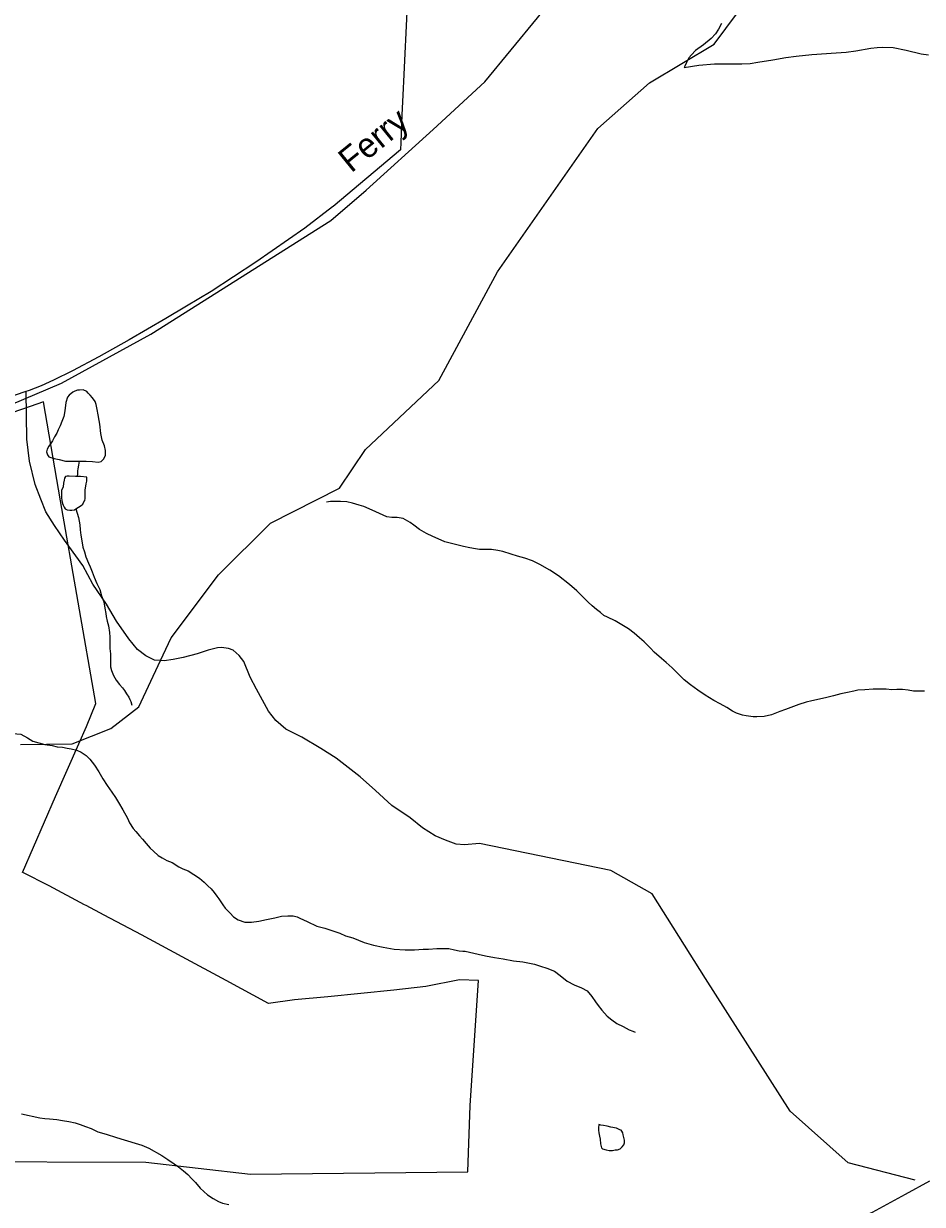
# Model space of a CAD drawing. Extents: x 2001466 to 2224147, y 644118 to 847247.
# Drawn here: x 2037237 to 2040702, y 678885 to 683440 of the extents above; entities that cross this region are included whole.
import ezdxf

# ---------------------------------------------------------------- set-up
doc = ezdxf.new("R2010")
doc.units = 0
for name, color, linetype in [('Exist Boundary Political City Limit New', 7, 'Continuous'), ('Exist Hydrographic Creek Single Shore', 7, 'Continuous'), ('Exist Hydrographic Misc Water Feature', 7, 'Continuous'), ('Exist Road Non-System Type 51', 7, 'Continuous'), ('Exist Road Secondary Type 51 Attributed', 7, 'Continuous'), ('Exist Road Secondary Type 51 Label', 7, 'Continuous'), ('Map Preparation Boundary City Limit Buffer Line', 7, 'Continuous')]:
    doc.layers.add(name, color=color, linetype=linetype)

msp = doc.modelspace()

# ---------------------------------------------------------------- linework, layer by layer
at = {"layer": 'Exist Boundary Political City Limit New'}
for points in [[(2038714.6, 683485), (2038710.9, 683404.7), (2038707.1, 683324.4), (2038703.2, 683244), (2038699.6, 683163.7), (2038696, 683087.9), (2038691, 682980.7), (2038689.8, 682952.9), (2038430.9, 682734.6), (2038428.2, 682732.4), (2038321.1, 682650.8), (2038132.5, 682519), (2037960.8, 682406.2), (2037865.8, 682349.6), (2037786.2, 682302.3), (2037644.4, 682220.5), (2037526.8, 682154.3), (2037426.1, 682100.1), (2037353.2, 682064.7), (2037305.1, 682042.2), (2037258.2, 682024.7), (2037242.6, 682018.8), (2037174.8, 681995.6)], [(2037233.6, 680165.6), (2037360.4, 680457.7), (2037450.4, 680661.2), (2037479.5, 680728.1), (2037515.2, 680816.6), (2037379.6, 681598.4), (2037314, 681981.4), (2037262.9, 681962.2), (2037192.5, 681938.2)], [(2036944.8, 679049.9), (2037709, 679048.1), (2038111.9, 679001), (2038950.1, 679011), (2038959.2, 679266.2), (2038990.4, 679748.1), (2038917.5, 679751), (2038787.4, 679725.1), (2038664.1, 679711.7), (2038410.5, 679685.1), (2038281.6, 679673.3), (2038181.6, 679660.1), (2038018.1, 679748.5), (2037848.8, 679840.4), (2037691.6, 679925.2), (2037547.5, 680000), (2037478, 680037.8), (2037472.6, 680040.6), (2037336.1, 680113.2), (2037234.4, 680165.2)]]:
    msp.add_lwpolyline(points, dxfattribs=at)
at = {"layer": 'Exist Hydrographic Creek Single Shore'}
for points in [[(2039064.6, 682482.2), (2039450.9, 683035.3), (2039650, 683211.6), (2039900, 683360.8), (2040165.9, 683719.5), (2040258, 683852.2), (2040365.8, 683945.1), (2040957, 684172.6), (2041223, 684314.8), (2041464.9, 684290.2), (2041972.8, 684138.8), (2042122.9, 684057), (2042673.9, 683924.4), (2043115, 683967.9), (2043248.9, 683952.1), (2043339.9, 683884.6), (2043432.8, 683577.6)], [(2037988.9, 681312.9), (2038188.8, 681512.3), (2038455, 681647.9), (2038554.8, 681796.8), (2038837.8, 682063.4), (2039064.6, 682482.2)], [(2037765.1, 680982.7), (2037806, 681070.5), (2037988.9, 681312.9)], [(2037225.9, 680659.1), (2037424, 680661.6), (2037573.8, 680720.9), (2037681.9, 680804), (2037765.1, 680982.7)]]:
    msp.add_lwpolyline(points, dxfattribs=at)
at = {"layer": 'Exist Hydrographic Misc Water Feature'}
for points in [[(2039927.8, 683440.2), (2039915.9, 683418.2), (2039904.1, 683400.2), (2039888.1, 683382.2), (2039858.1, 683358.1), (2039828.2, 683336.1), (2039812.2, 683320), (2039802.1, 683308), (2039792.3, 683290), (2039786.4, 683276), (2039784.3, 683270)], [(2039784.3, 683270), (2039840.3, 683280.1), (2039900.4, 683284.2), (2039948.3, 683284.3), (2040006.2, 683284.4), (2040038.2, 683286.4), (2040068.1, 683290.5), (2040126.1, 683300.6), (2040176.2, 683308.7), (2040216.1, 683314.8), (2040276.2, 683320.9), (2040369.9, 683327.1), (2040408.1, 683329.1), (2040446, 683335.2), (2040504, 683345.3), (2040528, 683347.4), (2040550, 683349.4), (2040590, 683347.5), (2040640, 683337.6), (2040698, 683323.7), (2040726.1, 683319.8)], [(2037451, 681752.5), (2037479.1, 681752.5), (2037503.1, 681750.6), (2037525, 681748.6), (2037536.9, 681750.7), (2037547, 681760.7), (2037552.9, 681774.6), (2037552.9, 681792.6), (2037548.8, 681810.6), (2037540.8, 681832.6), (2037534.7, 681858.6), (2037530.8, 681894.6), (2037528.7, 681908.6), (2037524.6, 681930.6), (2037520.7, 681950.6), (2037516.6, 681970.6), (2037512.7, 681982.5), (2037502.5, 681996.5), (2037494.5, 682006.5), (2037486.5, 682014.5), (2037480.5, 682020.5), (2037466.6, 682026.5), (2037452.5, 682026.4), (2037444.5, 682026.4), (2037434.6, 682022.4), (2037426.6, 682018.4), (2037412.5, 682006.3), (2037406.5, 681998.3), (2037400.6, 681978.3), (2037396.7, 681946.3), (2037392.8, 681924.3), (2037384.8, 681904.3), (2037378.8, 681888.3), (2037370.8, 681872.3), (2037364.9, 681860.3), (2037356.9, 681846.3), (2037348.9, 681830.3), (2037340.9, 681818.3), (2037335, 681810.3), (2037328.8, 681798.2), (2037325.1, 681788.2), (2037329, 681776.3), (2037335, 681768.2), (2037355.1, 681762.2), (2037374.9, 681758.3), (2037398.9, 681752.4), (2037427, 681752.4), (2037451, 681752.5)], [(2037451, 681752.5), (2037449, 681736.5), (2037446.9, 681722.5), (2037445.1, 681714.5), (2037445.1, 681704.5), (2037443.2, 681692.5)], [(2037443.2, 681692.5), (2037437.1, 681692.5), (2037413.1, 681694.4), (2037405.1, 681694.4), (2037399.1, 681692.4), (2037395, 681686.4), (2037393.2, 681678.4), (2037391.1, 681666.4), (2037389.3, 681652.4), (2037383.4, 681638.3), (2037383.4, 681626.4), (2037383.4, 681610.4), (2037385.2, 681600.4), (2037387.2, 681588.4), (2037389.3, 681582.4), (2037393.4, 681574.4), (2037397.3, 681568.4), (2037405.3, 681564.4), (2037415.3, 681562.5), (2037423.3, 681562.5), (2037433.4, 681564.5), (2037439.3, 681568.5)], [(2037439.3, 681568.5), (2037459.2, 681580.5), (2037465.2, 681586.5), (2037469.3, 681594.5), (2037473.2, 681600.5), (2037475.2, 681608.5), (2037475.2, 681624.5), (2037475.2, 681640.5), (2037479.1, 681664.5), (2037481.2, 681674.5), (2037481.2, 681682.5), (2037481.2, 681686.5), (2037481.2, 681690.5), (2037457.2, 681692.5), (2037443.2, 681692.5)], [(2037439.3, 681568.5), (2037449.4, 681534.5), (2037453.5, 681506.5), (2037455.5, 681486.5), (2037457.6, 681466.5), (2037461.5, 681444.5), (2037465.6, 681420.5), (2037471.7, 681402.6), (2037477.7, 681382.6), (2037487.7, 681358.6), (2037493.7, 681344.6), (2037501.7, 681324.7), (2037509.7, 681304.7), (2037519.9, 681280.6), (2037531.8, 681256.7), (2037538, 681232.7), (2037546, 681208.7), (2037550.1, 681184.8), (2037554, 681164.8), (2037556.2, 681152.8), (2037560.1, 681134.8), (2037564.2, 681116.8), (2037568.3, 681090.7), (2037570.2, 681072.8), (2037570.2, 681052.8), (2037570.2, 681028.8), (2037572.4, 681008.8), (2037572.4, 680992.8), (2037572.4, 680974.8), (2037572.4, 680958.8), (2037576.5, 680944.9), (2037584.5, 680924.8), (2037594.6, 680906.9), (2037606.4, 680890.9), (2037618.5, 680876.9), (2037626.5, 680866.9), (2037634.5, 680854.9), (2037642.5, 680840.9), (2037646.6, 680832.9), (2037650.5, 680824.9), (2037654.2, 680810.9)], [(2038957.3, 681417.3), (2038933.3, 681423.2), (2038917.3, 681427.2), (2038881.5, 681435.2), (2038861.4, 681441.1), (2038847.4, 681447.1), (2038815.2, 681461), (2038791.2, 681473), (2038763.1, 681488.9), (2038741.2, 681504.9), (2038727.3, 681514.8), (2038701.2, 681530.8), (2038677.2, 681534.8), (2038657.3, 681534.7), (2038637.2, 681536.7), (2038595.2, 681556.6), (2038569.2, 681568.5), (2038549.1, 681576.5), (2038531, 681582.5), (2038505.2, 681590.4), (2038483, 681594.4), (2038459.1, 681596.4), (2038441.2, 681596.4), (2038421.1, 681596.3), (2038405.1, 681594.2)], [(2040710.1, 680864.6), (2040692.1, 680864.6), (2040668.1, 680864.6), (2040648, 680868.5), (2040626, 680870.5), (2040604.1, 680870.5), (2040584, 680870.4), (2040562.1, 680872.4), (2040540.1, 680872.3), (2040512, 680872.3), (2040480, 680870.2), (2040454, 680868.2), (2040438, 680864.2), (2040414, 680860.1), (2040388.2, 680854), (2040360.1, 680846), (2040334.3, 680840), (2040306.2, 680833.9), (2040276.2, 680827.8), (2040254.3, 680821.8), (2040226.2, 680813.8), (2040174.3, 680793.6), (2040152.4, 680785.6), (2040120.4, 680773.6), (2040092.3, 680767.5), (2040064.4, 680765.4), (2040050.3, 680765.4), (2040022.4, 680769.4), (2040008.4, 680771.4), (2039986.3, 680779.3), (2039970.3, 680787.3), (2039948.3, 680801.3), (2039922.3, 680815.2), (2039898.3, 680829.2), (2039864.3, 680849), (2039836.2, 680869), (2039808.3, 680888.9), (2039784.1, 680908.9), (2039760.1, 680932.9), (2039738.2, 680954.8), (2039714, 680974.7), (2039695.9, 680990.7), (2039668, 681014.7), (2039653.9, 681030.7), (2039629.9, 681054.6), (2039611.9, 681070.5), (2039591.8, 681088.5), (2039569.8, 681104.5), (2039543.8, 681120.4), (2039517.7, 681136.4), (2039487.8, 681150.3), (2039473.7, 681156.3), (2039461.8, 681168.3), (2039445.8, 681180.3), (2039429.8, 681194.2), (2039413.6, 681208.2), (2039391.6, 681230.1), (2039369.7, 681252.1), (2039341.4, 681276.1), (2039299.6, 681309.9), (2039265.5, 681331.9), (2039227.4, 681353.8), (2039199.3, 681367.7), (2039169.4, 681377.7), (2039141.3, 681385.7), (2039117.3, 681393.6), (2039085.3, 681403.6), (2039065.4, 681407.5), (2039041.4, 681411.5), (2039015.4, 681411.4), (2038995.3, 681411.3), (2038979.3, 681413.3), (2038957.3, 681417.3)], [(2037060.4, 680687.1), (2037083.6, 680694), (2037101.6, 680700.1), (2037127.4, 680704.6), (2037157.4, 680704), (2037179.5, 680702.7), (2037211.5, 680700.4), (2037226.9, 680699.3), (2037252.9, 680684.3), (2037273, 680672.3), (2037319, 680658.4), (2037347.1, 680654.4), (2037366.9, 680650.5), (2037387, 680648.5)], [(2037387, 680648.5), (2037404.9, 680644.6), (2037421.1, 680642.6), (2037443, 680636.7), (2037459, 680628.7), (2037479.1, 680616.7), (2037493.1, 680602.7), (2037511.1, 680578.8), (2037527.1, 680552.8), (2037543.3, 680526.9), (2037559.3, 680500.9), (2037577.3, 680474.9), (2037591.3, 680454.9), (2037603.4, 680434.9), (2037619.4, 680407), (2037637.4, 680375), (2037645.4, 680357), (2037659.6, 680335.1), (2037669.6, 680323.1), (2037683.5, 680307.1), (2037695.6, 680293.1), (2037709.6, 680277.2), (2037725.6, 680259.2), (2037737.7, 680247.2), (2037755.7, 680231.3), (2037771.7, 680221.3), (2037789.8, 680211.3), (2037809.7, 680203.4), (2037835.7, 680187.4), (2037851.7, 680179.4), (2037871.8, 680171.6), (2037893.9, 680157.5), (2037915.9, 680143.6), (2037933.9, 680127.7), (2037947.9, 680113.7), (2037959.8, 680101.6), (2037972.1, 680087.7), (2037981.9, 680073.7), (2037989.9, 680063.7), (2038005.9, 680039.8), (2038013.9, 680027.8), (2038034, 680007.8), (2038046.1, 679993.8), (2038064.1, 679981.9), (2038090.2, 679973.9), (2038116, 679974), (2038144.1, 679978), (2038174, 679984.1), (2038206, 679990.2), (2038232.1, 679996.2), (2038256.1, 679998.2), (2038276.1, 679998.3), (2038292.1, 679994.3), (2038302, 679988.3), (2038330.1, 679976.4), (2038368, 679958.4), (2038398.2, 679950.6), (2038430.1, 679940.6), (2038456, 679930.6), (2038478.1, 679920.7), (2038506.2, 679912.7), (2038550.1, 679894.8), (2038586.2, 679884.8), (2038624.1, 679876.9), (2038666.2, 679869), (2038708.2, 679867.1), (2038744.3, 679867.2), (2038778.1, 679869.3), (2038798.2, 679869.3), (2038830.2, 679871.3), (2038852.1, 679871.4), (2038876.1, 679871.4), (2038898.3, 679867.4), (2038916.1, 679863.5), (2038930.3, 679861.5), (2038940.1, 679861.6), (2038990.1, 679849.6), (2039018.2, 679843.7), (2039052.3, 679837.7), (2039086.1, 679831.8), (2039126.3, 679823.9), (2039162.2, 679819.9), (2039206.3, 679812), (2039230.3, 679804), (2039254.2, 679796.1), (2039284.2, 679784.2), (2039306.3, 679768.3), (2039332.4, 679746.2), (2039360.3, 679732.3), (2039388.4, 679720.4), (2039410.3, 679708.4), (2039428.3, 679686.4), (2039442.5, 679666.5), (2039452.5, 679652.5), (2039466.5, 679634.6), (2039486.6, 679610.6), (2039504.6, 679596.6), (2039524.5, 679582.7), (2039548.5, 679570.7), (2039572.5, 679558.8)], [(2039572.5, 679558.8), (2039586.6, 679552.8), (2039594.6, 679548.8)], [(2037228.7, 679234.3), (2037299.5, 679218.6), (2037319.6, 679216.6), (2037337.6, 679214.6), (2037365.5, 679212.7), (2037387.7, 679208.8), (2037411.6, 679204.8), (2037435.6, 679198.8), (2037455.5, 679192.9), (2037475.6, 679184.9), (2037497.8, 679176.9), (2037523.6, 679165), (2037555.6, 679155.1), (2037595.8, 679143.2), (2037667.8, 679121.3), (2037693.6, 679113.3), (2037719.6, 679101.4), (2037769.9, 679073.4), (2037793.9, 679057.5), (2037817.9, 679041.6), (2037833.9, 679029.6), (2037853.9, 679013.7), (2037869.9, 678999.7), (2037885.9, 678983.7), (2037899.9, 678969.8), (2037917.9, 678947.8), (2037932.1, 678933.9), (2037946, 678921.9), (2037968, 678907.9), (2037988.1, 678895.9), (2038004, 678890), (2038028, 678884)], [(2039453.4, 679170.6), (2039455.2, 679160.6), (2039457.2, 679148.6), (2039459.5, 679136.6), (2039461.3, 679118.6), (2039463.4, 679108.6), (2039465.5, 679102.6), (2039469.3, 679098.6), (2039483.5, 679094.7), (2039495.4, 679092.7), (2039507.5, 679092.7), (2039517.3, 679094.8), (2039527.4, 679094.8), (2039537.4, 679098.8), (2039545.4, 679106.8), (2039551.4, 679114.8), (2039553.4, 679122.8), (2039553.4, 679132.8), (2039551.4, 679142.8), (2039549.3, 679152.7), (2039547.3, 679160.7), (2039543.4, 679166.7), (2039541.3, 679170.7), (2039535.4, 679172.7), (2039523.3, 679178.7), (2039501.3, 679182.7), (2039487.4, 679186.7), (2039473.2, 679188.6), (2039463.2, 679190.6), (2039455.2, 679192.6), (2039453.4, 679180.6), (2039453.4, 679170.6)]]:
    msp.add_lwpolyline(points, dxfattribs=at)
at = {"layer": 'Exist Road Non-System Type 51'}
for points in [[(2037765.1, 680982.7), (2037741.9, 680984.3), (2037708.2, 681001), (2037676.7, 681025.7), (2037643.6, 681066.3), (2037595, 681135.3), (2037556.3, 681200.1), (2037503.9, 681277.2), (2037465.3, 681350), (2037438.1, 681386.5), (2037395.3, 681447.4), (2037356.5, 681504.2), (2037323.6, 681556.8), (2037303.8, 681605.3), (2037281.7, 681661.7), (2037259.5, 681752.2), (2037249.2, 681836.4), (2037247, 682020.4)], [(2040675.1, 678978.8), (2040416.6, 679045.3), (2040192.4, 679243.9), (2039865.8, 679756.6), (2039660.8, 680083.4), (2039500.7, 680173.1), (2038995.5, 680276.9), (2038937.4, 680272.1), (2038905.5, 680274.7), (2038863.8, 680289.6), (2038824.1, 680306.4), (2038774.7, 680337.4), (2038727.5, 680376.3), (2038656.5, 680423.8), (2038593.7, 680481.1), (2038534.7, 680534.2), (2038442.2, 680606.1), (2038383, 680643.3), (2038309.9, 680686.8), (2038248.5, 680718.1), (2038209.2, 680750.9), (2038181.9, 680787.4), (2038135.6, 680872.4), (2038110.6, 680918.9), (2038085.8, 680979.4), (2038068.3, 681001.7), (2038044.7, 681022.2), (2038026.8, 681028.6), (2038000.9, 681033.1), (2037984.9, 681031.4), (2037948.7, 681022.2), (2037906.4, 681009), (2037852.1, 680994.1), (2037814, 680986.9), (2037779.8, 680981.6), (2037765.1, 680982.7)]]:
    msp.add_lwpolyline(points, dxfattribs=at)
at = {"layer": 'Exist Road Secondary Type 51 Attributed'}
for points in [[(2037187.4, 681968.8), (2037383.7, 682053.3), (2037727.8, 682241.3), (2038421.4, 682680.8), (2038558.6, 682797), (2038816.2, 683031.5), (2039015.7, 683215.3), (2039218.4, 683462.5), (2039461.2, 683764.6), (2039707.1, 684032.9), (2039859.1, 684161.8), (2040139.9, 684360.4), (2040346.8, 684489.2), (2040490.4, 684542), (2040794.4, 684590.6), (2041247.3, 684664.6), (2041817.3, 684738.5), (2042364.1, 684808.2), (2042732.5, 684873.7), (2043125.2, 684901.2), (2043528.4, 684956.1), (2043735.4, 684980.4)], [(2040729.4, 678974), (2040636, 678923.3), (2040509.3, 678853.6), (2040289.7, 678764.9), (2040114.5, 678682.5), (2040002.6, 678591.6), (2039729.2, 678359.2), (2039418.9, 678055), (2039250, 677898.7), (2038968.1, 677695.8), (2038801.3, 677588.1), (2038611.3, 677499.4), (2038459.3, 677414.9), (2038324.2, 677300.8), (2038161.6, 677121.2), (2038033.9, 676986), (2037795.3, 676728.2)]]:
    msp.add_lwpolyline(points, dxfattribs=at)
at = {"layer": 'Map Preparation Boundary City Limit Buffer Line'}
for points in [[(2038714.6, 683485), (2038710.9, 683404.7), (2038707.1, 683324.4), (2038703.2, 683244), (2038699.6, 683163.7), (2038696, 683087.9), (2038691, 682980.7), (2038689.8, 682952.9), (2038430.9, 682734.6), (2038428.2, 682732.4), (2038321.1, 682650.8), (2038132.5, 682519), (2037960.8, 682406.2), (2037865.8, 682349.6), (2037786.2, 682302.3), (2037644.4, 682220.5), (2037526.8, 682154.3), (2037426.1, 682100.1), (2037353.2, 682064.7), (2037305.1, 682042.2), (2037258.2, 682024.7), (2037242.6, 682018.8), (2037174.8, 681995.6)], [(2037233.6, 680165.6), (2037360.4, 680457.7), (2037450.4, 680661.2), (2037479.5, 680728.1), (2037515.2, 680816.6), (2037379.6, 681598.4), (2037314, 681981.4), (2037262.9, 681962.2), (2037192.5, 681938.2)], [(2036944.8, 679049.9), (2037709, 679048.1), (2038111.9, 679001), (2038950.1, 679011), (2038959.2, 679266.2), (2038990.4, 679748.1), (2038917.5, 679751), (2038787.4, 679725.1), (2038664.1, 679711.7), (2038410.5, 679685.1), (2038281.6, 679673.3), (2038181.6, 679660.1), (2038018.1, 679748.5), (2037848.8, 679840.4), (2037691.6, 679925.2), (2037547.5, 680000), (2037478, 680037.8), (2037472.6, 680040.6), (2037336.1, 680113.2), (2037234.4, 680165.2)]]:
    msp.add_lwpolyline(points, dxfattribs=at)

# ---------------------------------------------------------------- texts
at = {"layer": 'Exist Road Secondary Type 51 Label'}
msp.add_text('Ferry', height=95, rotation=39.07, dxfattribs=at).set_placement((2038500.2, 682861.4))

doc.saveas('drawing.dxf')
